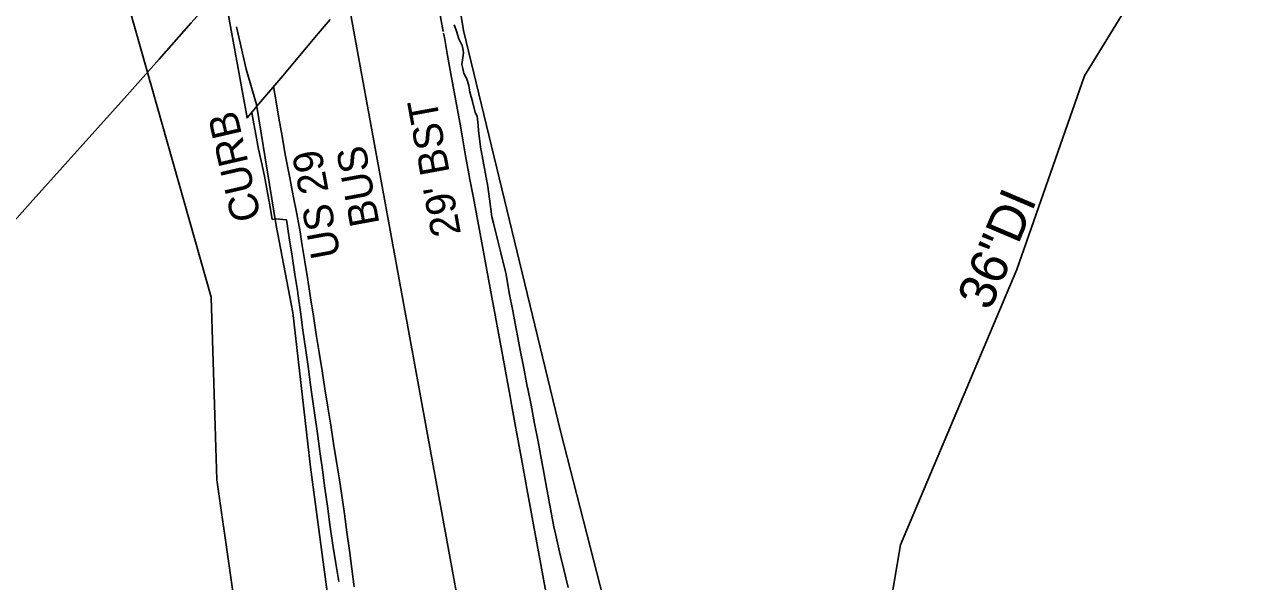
# Model space of a CAD drawing. Extents: x 1806071 to 1809844, y 912722 to 917035.
# Drawn here: x 1807709.9 to 1807877.5, y 915678.1 to 915753.7 of the extents above; entities that cross this region are included whole.
import ezdxf

# ---------------------------------------------------------------- set-up
doc = ezdxf.new("R2010")
doc.units = 0
for name, color, linetype in [('Exist Guardrail', 7, 'Continuous'), ('Exist Horizontal Alignment', 7, 'Continuous'), ('Exist Railroads Standard Gauge', 7, 'Continuous'), ('Exist Right of Way Line', 7, 'Continuous'), ('Exist Roads Curbs', 7, 'Continuous'), ('Exist Roads Curbs Text', 7, 'Continuous'), ('Exist Roads EOP', 7, 'Continuous'), ('Exist Roads EOT', 7, 'Continuous'), ('Exist Roads EOT Text', 7, 'Continuous'), ('Exist Structure Major Deck Tunnel Box Culvert', 7, 'Continuous'), ('Exist Utilities Water UG Line SUE LOS B', 7, 'Continuous'), ('Exist Utilities Water UG Line SUE LOS B Text', 7, 'Continuous'), ('Exist Vegetation Woods Line', 7, 'Continuous')]:
    doc.layers.add(name, color=color, linetype=linetype)

msp = doc.modelspace()

# ---------------------------------------------------------------- linework, layer by layer
at = {"layer": 'Exist Guardrail'}
for points in [[(1807764.45, 915784.13), (1807769.59, 915752.88), (1807782.77, 915698.48), (1807793.5, 915656.64), (1807805.06, 915608.64), (1807810.31, 915590.66), (1807813.42, 915573.71)], [(1807759.76, 915589.01), (1807756.64, 915624.73), (1807752.18, 915668.16), (1807748.8, 915693.57), (1807746.39, 915714.58), (1807744.12, 915726.4), (1807741.44, 915742.84), (1807740.06, 915747.64), (1807738.75, 915753.38)]]:
    msp.add_lwpolyline(points, dxfattribs=at)
at = {"layer": 'Exist Horizontal Alignment'}
msp.add_line((1807771.97, 915658.33), (1807748.29, 915787.67), dxfattribs=at)
msp.add_arc((1805206.16, 917989.46), 3323.5, 313.68156, 325.82407, dxfattribs=at)
at = {"layer": 'Exist Railroads Standard Gauge'}
msp.add_arc((1805206.16, 917989.46), 3323.5, 298.4006, 325.82407, dxfattribs=at)
at = {"layer": 'Exist Right of Way Line'}
for radius, end in [(3173.5, 327.00081), (3373.5, 326.99746)]:
    msp.add_arc((1805206.16, 917989.46), radius, 298.4006, end, dxfattribs=at)
at = {"layer": 'Exist Roads Curbs'}
for points in [[(1807740.81, 915741.75), (1807740.99, 915740.71), (1807741.35, 915738.74), (1807741.72, 915736.78), (1807742.23, 915734.58)], [(1807743.56, 915727.19), (1807743.26, 915729.16), (1807742.91, 915731.12), (1807742.53, 915733.08), (1807742.23, 915734.56)]]:
    msp.add_lwpolyline(points, dxfattribs=at)
at = {"layer": 'Exist Roads EOP'}
for points in [[(1807768.32, 915753.66), (1807768.63, 915752.77), (1807768.94, 915751.75), (1807769.39, 915750.85), (1807769.5, 915750.43), (1807769.56, 915749.85), (1807769.45, 915748.89), (1807769.36, 915748.27), (1807769.48, 915747.71), (1807769.61, 915747.04), (1807769.99, 915746.42), (1807770.3, 915745.39), (1807770.46, 915744.48), (1807770.79, 915743.25), (1807771.17, 915741.75), (1807771.46, 915741.26), (1807771.57, 915740.04)], [(1807783.79, 915677.22), (1807783.22, 915679.66), (1807782.65, 915682.09), (1807782.08, 915684.53), (1807781.86, 915685.46), (1807781.41, 915687.92), (1807780.96, 915690.38), (1807780.51, 915692.84), (1807780.06, 915695.3), (1807779.74, 915697.07), (1807779.25, 915699.52), (1807778.76, 915701.98), (1807778.28, 915704.43), (1807778.25, 915704.55), (1807777.77, 915707), (1807777.29, 915709.46), (1807776.81, 915711.91), (1807776.72, 915712.34), (1807776.27, 915714.8), (1807775.81, 915717.26), (1807775.36, 915719.72), (1807775.25, 915720.27), (1807774.65, 915722.7), (1807774.26, 915724.29), (1807773.64, 915726.72), (1807773.43, 915727.55), (1807773.1, 915730.03), (1807772.87, 915731.68), (1807772.43, 915734.14), (1807771.99, 915736.6), (1807771.96, 915736.76), (1807771.64, 915739.24), (1807771.57, 915740.02)], [(1807743.57, 915727.19), (1807744.08, 915727.28), (1807745.52, 915727.17), (1807745.9, 915724.7), (1807746.29, 915722.23), (1807746.67, 915719.76), (1807747.06, 915717.29), (1807747.08, 915717.15), (1807747.42, 915714.68), (1807747.77, 915712.2), (1807748.11, 915709.72), (1807748.46, 915707.25), (1807748.8, 915704.77), (1807749.03, 915703.12), (1807749.38, 915700.64), (1807749.72, 915698.17), (1807750.07, 915695.69), (1807750.41, 915693.21), (1807750.75, 915690.74), (1807751.1, 915688.26), (1807751.44, 915685.78), (1807751.78, 915683.31), (1807751.83, 915682.98), (1807752.24, 915680.51), (1807752.65, 915678.04)]]:
    msp.add_lwpolyline(points, dxfattribs=at)
at = {"layer": 'Exist Roads EOT'}
for points in [[(1807766.82, 915752.76), (1807766.37, 915755.22), (1807765.93, 915757.68), (1807765.48, 915760.14), (1807765.04, 915762.6), (1807764.59, 915765.06), (1807763.87, 915769.04)], [(1807769.2, 915739.65), (1807768.76, 915742.09), (1807768.32, 915744.55), (1807767.88, 915747.01), (1807767.43, 915749.47), (1807766.99, 915751.93), (1807766.88, 915752.51)], [(1807743.77, 915745.25), (1807744.08, 915743.44), (1807744.5, 915740.98), (1807744.93, 915738.52), (1807745.36, 915736.05), (1807745.43, 915735.61)], [(1807780.89, 915675.92), (1807780.44, 915678.38), (1807780, 915680.84), (1807779.55, 915683.3), (1807779.11, 915685.76), (1807778.66, 915688.22), (1807778.21, 915690.68), (1807777.93, 915692.23), (1807777.48, 915694.69), (1807777.03, 915697.15), (1807776.58, 915699.61), (1807776.12, 915702.07), (1807775.92, 915703.17), (1807775.47, 915705.63), (1807775.02, 915708.09), (1807774.56, 915710.55), (1807774.11, 915713), (1807773.66, 915715.46), (1807773.22, 915717.88), (1807772.76, 915720.34), (1807772.3, 915722.8), (1807771.84, 915725.25), (1807771.38, 915727.71), (1807770.92, 915730.17), (1807770.46, 915732.63), (1807770.31, 915733.39), (1807769.87, 915735.85), (1807769.43, 915738.31), (1807769.21, 915739.63)], [(1807754.74, 915677.31), (1807754.41, 915679.79), (1807754.07, 915682.27), (1807753.73, 915684.74), (1807753.39, 915687.22), (1807753.1, 915689.39), (1807752.71, 915691.86), (1807752.32, 915694.32), (1807751.93, 915696.79), (1807751.54, 915699.26), (1807751.15, 915701.73), (1807750.75, 915704.2), (1807750.36, 915706.67), (1807749.97, 915709.14), (1807749.58, 915711.61), (1807749.19, 915714.08), (1807748.8, 915716.55), (1807748.41, 915719.02), (1807748.02, 915721.49), (1807747.63, 915723.96), (1807747.38, 915725.52), (1807746.94, 915727.98), (1807746.45, 915730.43), (1807745.97, 915732.88), (1807745.44, 915735.6)]]:
    msp.add_lwpolyline(points, dxfattribs=at)
at = {"layer": 'Exist Structure Major Deck Tunnel Box Culvert'}
msp.add_lwpolyline([(1807751.47, 915754.36), (1807749.85, 915752.45), (1807748.24, 915750.55), (1807746.63, 915748.64), (1807745.01, 915746.73), (1807743.4, 915744.82), (1807741.79, 915742.91), (1807740.17, 915741), (1807732.99, 915780.47)], dxfattribs=at)
at = {"layer": 'Exist Utilities Water UG Line SUE LOS B'}
msp.add_lwpolyline([(1807836.21, 915492.88), (1807836.12, 915493.71), (1807836.57, 915507.83), (1807832.12, 915551.21), (1807826.47, 915602.28), (1807825.75, 915643.71), (1807825.65, 915663.54), (1807828.97, 915683.02), (1807844.78, 915720.42), (1807853.97, 915746.74), (1807867.47, 915768.73), (1807886.68, 915798.34), (1807896.7, 915817.61)], dxfattribs=at)
at = {"layer": 'Exist Vegetation Woods Line'}
msp.add_lwpolyline([(1807617.05, 915674.16), (1807701.28, 915763.8), (1807721.96, 915763.7), (1807735.31, 915716.67), (1807736.05, 915691.87), (1807739.7, 915666.61), (1807744.78, 915623.49), (1807741.38, 915579.01), (1807735.23, 915538.93), (1807721.35, 915515.08), (1807686.87, 915527.74), (1807679.19, 915490.58), (1807654.09, 915460.85), (1807652.76, 915434.08), (1807637.79, 915399.29), (1807621.12, 915382.49), (1807623.05, 915340.68), (1807609.29, 915294.27)], dxfattribs=at)

# ---------------------------------------------------------------- texts
at = {"layer": 'Exist Roads Curbs Text'}
msp.add_text('CURB', height=4, rotation=102.9861, dxfattribs=at).set_placement((1807742.1, 915727.42))
at = {"layer": 'Exist Roads EOT Text'}
for s, p in [("29' BST", (1807769.25, 915725.28)), ('US 29', (1807752.88, 915722.29)), ('BUS', (1807758.18, 915726.64))]:
    msp.add_text(s, height=4, rotation=100.4051, dxfattribs=at).set_placement(p)
at = {"layer": 'Exist Utilities Water UG Line SUE LOS B Text'}
msp.add_text('36"DI', height=5, rotation=67.0828, dxfattribs=at).set_placement((1807841.13, 915714.68))

doc.saveas('drawing.dxf')
